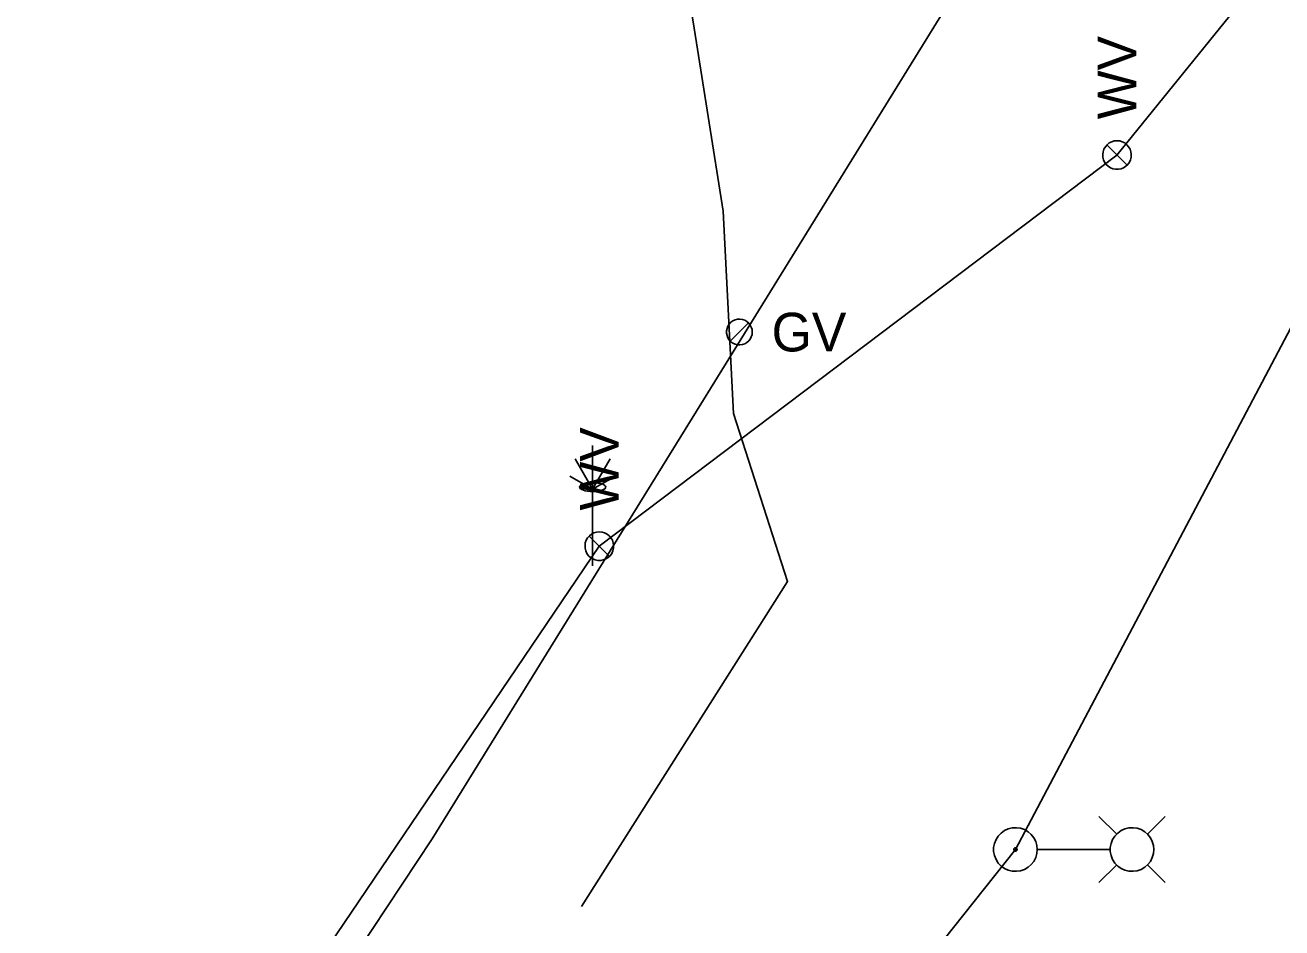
# Model space of a CAD drawing. Extents: x 596028 to 606371, y 330010 to 403088.
# Drawn here: x 604662.9 to 604787.9, y 330823.2 to 330913.1 of the extents above; entities that cross this region are included whole.
import ezdxf

# ---------------------------------------------------------------- set-up
doc = ezdxf.new("R2010")
doc.units = 0
for name, color, linetype in [('E_LTG', 7, 'Continuous'), ('E_MISCPROP_Sprinkler', 7, 'Continuous'), ('E_UTL_E_UG', 7, 'Continuous'), ('E_UTL_G', 7, 'Continuous'), ('E_UTL_G_UG', 7, 'Continuous'), ('E_UTL_W', 7, 'Continuous'), ('E_UTL_W_UG', 7, 'Continuous')]:
    doc.layers.add(name, color=color, linetype=linetype)

msp = doc.modelspace()

# ---------------------------------------------------------------- linework, layer by layer
at = {"layer": 'E_LTG'}
for points in [[(604771.48, 330832.49), (604769.7, 330834.27)], [(604774.53, 330832.49), (604776.31, 330834.27)], [(604763.58, 330830.97), (604763.54, 330831.38), (604763.42, 330831.78), (604763.23, 330832.14), (604762.97, 330832.47), (604762.66, 330832.74), (604762.3, 330832.95), (604761.91, 330833.08), (604761.5, 330833.14), (604761.09, 330833.12), (604760.69, 330833.02), (604760.31, 330832.85), (604759.98, 330832.61), (604759.69, 330832.31), (604759.47, 330831.97), (604759.31, 330831.58), (604759.23, 330831.18), (604759.23, 330830.76), (604759.31, 330830.36), (604759.47, 330829.97), (604759.69, 330829.62), (604759.98, 330829.32), (604760.31, 330829.08), (604760.69, 330828.91), (604761.09, 330828.81), (604761.5, 330828.8), (604761.91, 330828.85), (604762.3, 330828.99), (604762.66, 330829.2), (604762.97, 330829.47), (604763.23, 330829.79), (604763.42, 330830.16), (604763.54, 330830.56), (604763.58, 330830.97)], [(604775.18, 330830.97), (604775.14, 330831.38), (604775.02, 330831.78), (604774.83, 330832.14), (604774.58, 330832.47), (604774.27, 330832.74), (604773.91, 330832.95), (604773.52, 330833.08), (604773.11, 330833.14), (604772.69, 330833.12), (604772.29, 330833.02), (604771.92, 330832.85), (604771.58, 330832.61), (604771.29, 330832.31), (604771.07, 330831.97), (604770.92, 330831.58), (604770.84, 330831.18), (604770.84, 330830.76), (604770.92, 330830.36), (604771.07, 330829.97), (604771.29, 330829.62), (604771.58, 330829.32), (604771.92, 330829.08), (604772.29, 330828.91), (604772.69, 330828.81), (604773.11, 330828.8), (604773.52, 330828.85), (604773.91, 330828.99), (604774.27, 330829.2), (604774.58, 330829.47), (604774.83, 330829.79), (604775.02, 330830.16), (604775.14, 330830.56), (604775.18, 330830.97)], [(604761.57, 330830.97), (604761.56, 330831), (604761.55, 330831.03), (604761.54, 330831.06), (604761.52, 330831.08), (604761.5, 330831.1), (604761.47, 330831.12), (604761.44, 330831.13), (604761.41, 330831.13), (604761.38, 330831.13), (604761.35, 330831.13), (604761.32, 330831.11), (604761.29, 330831.09), (604761.27, 330831.07), (604761.25, 330831.04), (604761.24, 330831.02), (604761.23, 330830.98), (604761.23, 330830.95), (604761.24, 330830.92), (604761.25, 330830.89), (604761.27, 330830.87), (604761.29, 330830.84), (604761.32, 330830.82), (604761.35, 330830.81), (604761.38, 330830.8), (604761.41, 330830.8), (604761.44, 330830.81), (604761.47, 330830.82), (604761.5, 330830.83), (604761.52, 330830.85), (604761.54, 330830.88), (604761.55, 330830.91), (604761.56, 330830.94), (604761.57, 330830.97)], [(604770.79, 330830.97), (604763.61, 330830.97)], [(604771.48, 330829.45), (604769.7, 330827.67)], [(604774.53, 330829.45), (604776.31, 330827.67)]]:
    msp.add_lwpolyline(points, dxfattribs=at)
at = {"layer": 'E_MISCPROP_Sprinkler'}
for points in [[(604719.33, 330871.21), (604719.33, 330859.21)], [(604719.33, 330866.84), (604717.59, 330869.87)], [(604719.33, 330866.84), (604721.08, 330869.87)], [(604719.33, 330866.84), (604717.06, 330868.15)], [(604719.33, 330866.84), (604721.6, 330868.15)]]:
    msp.add_lwpolyline(points, dxfattribs=at)
msp.add_ellipse((604719.33, 330867.06), major_axis=(1.31, 0), ratio=0.333333, dxfattribs=at)
at = {"layer": 'E_UTL_E_UG'}
for points in [[(604695.73, 330748.29), (604684.95, 330755.93), (604681.24, 330750.97), (604664.85, 330762.93), (604668.47, 330767.86), (604688.35, 330805.65), (604694.41, 330818.48), (604703.37, 330832.03), (604758.06, 330920.64), (604761.47, 330923.51), (604832.36, 331051.66)], [(604695.73, 330748.29), (604761.4, 330830.97), (604799.82, 330903.8), (604805.91, 330901.32)]]:
    msp.add_lwpolyline(points, dxfattribs=at)
at = {"layer": 'E_UTL_G'}
for points in [[(604735.21, 330882.5), (604735.19, 330882.74), (604735.12, 330882.98), (604735.01, 330883.19), (604734.86, 330883.38), (604734.67, 330883.54), (604734.46, 330883.67), (604734.23, 330883.75), (604733.99, 330883.78), (604733.75, 330883.77), (604733.51, 330883.71), (604733.29, 330883.61), (604733.09, 330883.47), (604732.92, 330883.29), (604732.79, 330883.09), (604732.7, 330882.86), (604732.65, 330882.62), (604732.65, 330882.38), (604732.7, 330882.14), (604732.79, 330881.91), (604732.92, 330881.7), (604733.09, 330881.53), (604733.29, 330881.39), (604733.51, 330881.29), (604733.75, 330881.23), (604733.99, 330881.22), (604734.23, 330881.25), (604734.46, 330881.33), (604734.67, 330881.45), (604734.86, 330881.61), (604735.01, 330881.8), (604735.12, 330882.02), (604735.19, 330882.26), (604735.21, 330882.5)], [(604733.02, 330881.59), (604734.84, 330883.41)]]:
    msp.add_lwpolyline(points, dxfattribs=at)
at = {"layer": 'E_UTL_G_UG'}
msp.add_lwpolyline([(604718.21, 330825.28), (604738.73, 330857.66), (604733.36, 330874.38), (604732.32, 330894.54), (604729.33, 330913.4), (604725.16, 330938.36), (604752.74, 330988.13), (604778.16, 331035.55), (604788.31, 331057.65), (604805.53, 331094.16), (604828.8, 331144.07), (604848.89, 331191.36), (604869.57, 331244.15), (604888.61, 331295.88), (604900.58, 331325.56), (604922.44, 331394.24)], dxfattribs=at)
at = {"layer": 'E_UTL_W'}
for points in [[(604771.51, 330901.55), (604771.24, 330901.53), (604770.98, 330901.45), (604770.74, 330901.33), (604770.53, 330901.16), (604770.35, 330900.96), (604770.21, 330900.72), (604770.12, 330900.46), (604770.09, 330900.2), (604770.1, 330899.93), (604770.16, 330899.66), (604770.28, 330899.42), (604770.43, 330899.19), (604770.63, 330899.01), (604770.86, 330898.86), (604771.11, 330898.76), (604771.37, 330898.71), (604771.65, 330898.71), (604771.91, 330898.76), (604772.16, 330898.86), (604772.39, 330899.01), (604772.59, 330899.19), (604772.75, 330899.42), (604772.86, 330899.66), (604772.92, 330899.93), (604772.93, 330900.2), (604772.9, 330900.46), (604772.81, 330900.72), (604772.67, 330900.96), (604772.49, 330901.16), (604772.28, 330901.33), (604772.04, 330901.45), (604771.78, 330901.53), (604771.51, 330901.55)], [(604772.52, 330899.12), (604770.5, 330901.14)], [(604719.99, 330862.59), (604719.72, 330862.57), (604719.46, 330862.49), (604719.22, 330862.37), (604719.01, 330862.2), (604718.83, 330862), (604718.69, 330861.76), (604718.6, 330861.5), (604718.57, 330861.24), (604718.58, 330860.97), (604718.64, 330860.7), (604718.76, 330860.46), (604718.91, 330860.23), (604719.11, 330860.05), (604719.34, 330859.9), (604719.59, 330859.8), (604719.85, 330859.75), (604720.13, 330859.75), (604720.39, 330859.8), (604720.64, 330859.9), (604720.87, 330860.05), (604721.07, 330860.23), (604721.23, 330860.46), (604721.34, 330860.7), (604721.4, 330860.97), (604721.41, 330861.24), (604721.38, 330861.5), (604721.29, 330861.76), (604721.15, 330862), (604720.97, 330862.2), (604720.76, 330862.37), (604720.52, 330862.49), (604720.26, 330862.57), (604719.99, 330862.59)], [(604721, 330860.16), (604718.98, 330862.18)]]:
    msp.add_lwpolyline(points, dxfattribs=at)
at = {"layer": 'E_UTL_W_UG'}
msp.add_lwpolyline([(604662.85, 330776.78), (604719.99, 330861.17), (604771.51, 330900.13), (604792.62, 330926.22), (604804.59, 330947.13), (605054.68, 331381.7), (605055.13, 331442.45), (605044.65, 331474.36), (605047.01, 331851.63), (605038.36, 332278.66), (605035.8, 332410.28), (605072.23, 332411.32), (605076.98, 332411.12), (605079.88, 332411.16)], dxfattribs=at)

# ---------------------------------------------------------------- texts
at = {"layer": 'E_UTL_G'}
msp.add_text('GV', height=3.85, dxfattribs=at).set_placement((604737.14, 330880.57))
at = {"layer": 'E_UTL_W'}
for p in [(604773.44, 330903.69), (604721.92, 330864.73)]:
    msp.add_text('WV', height=3.85, rotation=90, dxfattribs=at).set_placement(p)

doc.saveas('drawing.dxf')
